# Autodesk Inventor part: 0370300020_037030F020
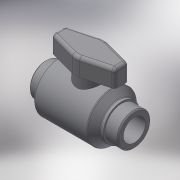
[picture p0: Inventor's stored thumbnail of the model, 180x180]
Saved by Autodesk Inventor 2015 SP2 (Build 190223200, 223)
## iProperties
Created: 2017-06
Part Number: 0370300020_037030F020
Material: Generic
Description: PLASSON BALL VALVE DN50 FEMALE 2" BSPT
Document SubType Name: Modeling
Designer: KIM
Mass: 187.868 g
Surface Area: 292.163 cm^2
Volume: 187.868 cm^3
Density: 1 g/cm^3
Appearance: Default
Author: KIM
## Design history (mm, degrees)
derived "03703.ipt"
feature "Solid1::03703.ipt"
tag "TaggingFeature1"
body "Solid1"
other parameters: "d0" = 162, "d3" = 106, "d4" = 29, "d5" = 56.656, "d6" = 56.656, "d7" = 29, "d8" = 75, "d9" = 23.2, "d10" = 82.5, "d11" = 15.0485, "d12" = 135 deg, "d14" = 2.8328, "d24" = 33.9936, "d25" = 68.9, "d27" = 33.9936, "d28" = 16.9968, "d29" = 28.1, "d30" = 0, "d32" = 74.78592, "d33" = 8.4984, "d34" = 2.8328, "Rc_" = 56.656, "A_1" = 53, "A_2" = 97, "H_" = 162, "l_" = 29, "B_" = 75, "E_" = 1, "d31" = 67.9872
